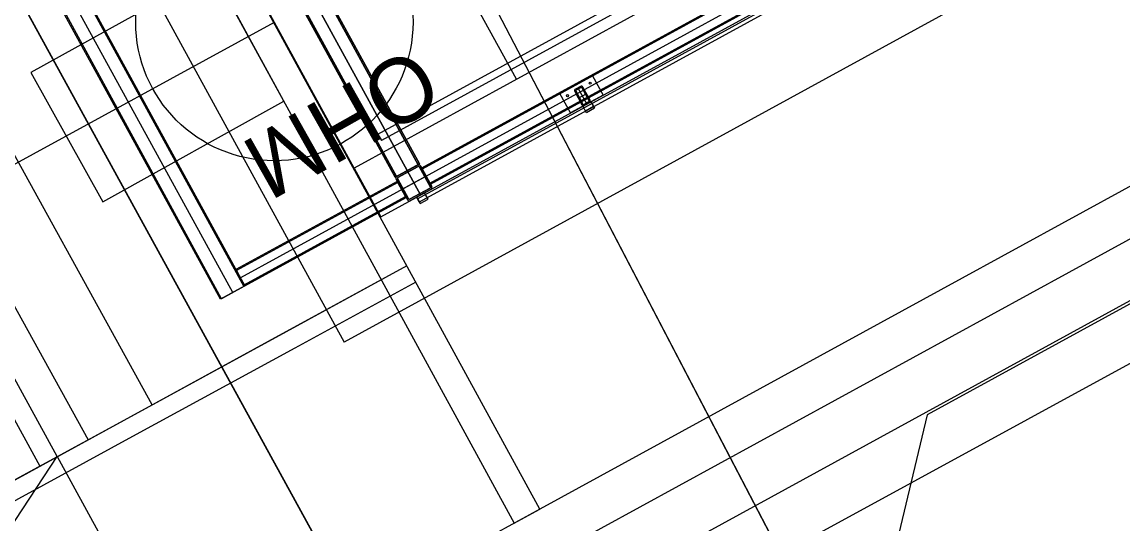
# Model space of a CAD drawing. Extents: x -783978 to -783565, y -1064821 to -1064596.
# Drawn here: x -783787.58 to -783781.62, y -1064696.42 to -1064693.71 of the extents above; entities that cross this region are included whole.
import ezdxf

# ---------------------------------------------------------------- set-up
doc = ezdxf.new("R2010")
doc.units = 0
for name, color, linetype in [('PS 01_01_10', 7, 'Continuous'), ('PS 01_02_501', 7, 'Continuous'), ('PS 01_02_502', 7, 'Continuous'), ('SO 01_20_01', 7, 'Continuous'), ('SO 01_50_01', 7, 'Continuous'), ('SO 01_74_01', 7, 'Continuous'), ('SO 01_79_02', 7, 'Continuous'), ('SO 01_86_02', 7, 'Continuous'), ('SO 01_86_03', 7, 'Continuous'), ('SO 01_86_04', 7, 'Continuous')]:
    doc.layers.add(name, color=color, linetype=linetype)

msp = doc.modelspace()

# ---------------------------------------------------------------- linework, layer by layer
at = {"layer": 'PS 01_01_10'}
msp.add_lwpolyline([(-783718.9415, -1064658.9356), (-783725.9639, -1064662.6889), (-783732.3538, -1064665.9121), (-783735.2095, -1064660.6967), (-783789.362, -1064690.3481), (-783783.8255, -1064700.4409), (-783871.4362, -1064748.4249), (-783875.857, -1064749.8347)], dxfattribs=at)
at = {"layer": 'PS 01_02_501'}
msp.add_lwpolyline([(-783952.3105, -1064789.972), (-783925.027, -1064771.233), (-783922.857, -1064767.935), (-783921.1315, -1064767.225), (-783922.344, -1064769.056), (-783920.816, -1064771.043), (-783917.67, -1064770.417), (-783911.05, -1064766.471), (-783887.429, -1064753.525), (-783871.4362, -1064748.4249), (-783783.8277, -1064700.4386), (-783789.362, -1064690.3481), (-783735.2263, -1064660.7067), (-783727.1901, -1064659.072), (-783724.297, -1064658.4835), (-783715.521, -1064653.988), (-783697.391, -1064644.148), (-783676.268, -1064633.506), (-783655.138, -1064621.894)], dxfattribs=at)
at = {"layer": 'PS 01_02_502'}
msp.add_lwpolyline([(-783952.3105, -1064789.972), (-783925.027, -1064771.233), (-783922.857, -1064767.935), (-783921.1315, -1064767.225), (-783922.344, -1064769.056), (-783920.816, -1064771.043), (-783917.67, -1064770.417), (-783911.05, -1064766.471), (-783887.429, -1064753.525), (-783871.4362, -1064748.4249), (-783783.8277, -1064700.4386), (-783789.362, -1064690.3481), (-783735.2263, -1064660.7067), (-783727.1901, -1064659.072), (-783724.297, -1064658.4835), (-783715.521, -1064653.988), (-783697.391, -1064644.148), (-783676.268, -1064633.506), (-783655.138, -1064621.894)], dxfattribs=at)
at = {"layer": 'SO 01_20_01'}
for p, q in [((-783785.6531, -1064694.3127), (-783737.23, -1064667.82)), ((-783737.0912, -1064667.858), (-783785.7805, -1064694.4964)), ((-783737.2108, -1064667.855), (-783785.6339, -1064694.3478)), ((-783785.6366, -1064694.7596), (-783736.9472, -1064668.1212)), ((-783746.2961, -1064673.8055), (-783785.8354, -1064695.4379)), ((-783787.4671, -1064692.4555), (-783785.8354, -1064695.4379)), ((-783784.9033, -1064694.0165), (-783785.7672, -1064692.4374)), ((-783785.7805, -1064694.4964), (-783786.6445, -1064692.9173)), ((-783785.6531, -1064694.3127), (-783785.6339, -1064694.3478)), ((-783785.6531, -1064694.3127), (-783785.6339, -1064694.3478)), ((-783785.7805, -1064694.4964), (-783785.6366, -1064694.7596))]:
    msp.add_line(p, q, dxfattribs=at)
at = {"layer": 'SO 01_50_01'}
for p, q in [((-783867.1634, -1064737.9103), (-783786.2125, -1064693.7069)), ((-783786.1479, -1064695.3806), (-783785.494, -1064695.0236)), ((-783786.1474, -1064695.3815), (-783785.4935, -1064695.0245)), ((-783786.1, -1064695.4684), (-783785.4461, -1064695.1114)), ((-783787.0256, -1064695.8599), (-783786.1479, -1064695.3806)), ((-783787.0251, -1064695.8608), (-783786.1474, -1064695.3815)), ((-783786.9776, -1064695.9477), (-783786.1, -1064695.4684)), ((-783787.9032, -1064696.3392), (-783787.0256, -1064695.8599)), ((-783787.9028, -1064696.34), (-783787.0251, -1064695.8608)), ((-783787.8553, -1064696.4269), (-783786.9776, -1064695.9477)), ((-783785.429, -1064696.6972), (-783784.7751, -1064696.3401))]:
    msp.add_line(p, q, dxfattribs=at)
for points in [[(-783784.7751, -1064696.3401), (-783745.2333, -1064674.7064)], [(-783784.6553, -1064696.5595), (-783745.1133, -1064674.9257)], [(-783787.3874, -1064696.0575), (-783791.2303, -1064689.0335)], [(-783791.318, -1064689.0815), (-783787.4804, -1064696.1094)], [(-783788.7043, -1064696.7753), (-783787.9847, -1064698.0929), (-783786.6685, -1064697.374), (-783788.3209, -1064697.4774), (-783787.3874, -1064696.0575), (-783786.6685, -1064697.374)]]:
    msp.add_lwpolyline(points, dxfattribs=at)
for points in [[(-783789.5438, -1064687.9418), (-783784.9159, -1064696.417), (-783784.7774, -1064696.3413), (-783789.41, -1064687.8687)], [(-783787.2188, -1064695.9666), (-783786.8738, -1064695.777), (-783790.6896, -1064688.851), (-783791.0399, -1064689.044)], [(-783786.5452, -1064693.4332), (-783787.5293, -1064693.9803), (-783787.1406, -1064694.6795), (-783786.1618, -1064694.1353)]]:
    msp.add_lwpolyline(points, close=True, dxfattribs=at)
msp.add_circle((-783786.2125, -1064693.7069), 0.75, dxfattribs=at)
at = {"layer": 'SO 01_74_01'}
for p, q in [((-783785.4388, -1064694.6628), (-783745.8293, -1064672.9921)), ((-783745.8197, -1064673.0096), (-783785.4292, -1064694.6803)), ((-783786.4428, -1064692.636), (-783785.4348, -1064694.4783)), ((-783785.4348, -1064694.4783), (-783786.4428, -1064692.636)), ((-783786.4358, -1064692.6321), (-783785.4278, -1064694.4744)), ((-783785.4278, -1064694.4744), (-783786.4358, -1064692.6321)), ((-783785.5594, -1064694.5464), (-783786.5674, -1064692.7041)), ((-783786.5674, -1064692.7041), (-783785.5594, -1064694.5464)), ((-783785.5524, -1064694.5426), (-783786.5603, -1064692.7003)), ((-783786.5603, -1064692.7003), (-783785.5524, -1064694.5426)), ((-783787.5067, -1064693.0734), (-783786.3776, -1064695.1372)), ((-783787.5012, -1064693.0704), (-783786.372, -1064695.1342)), ((-783786.5036, -1064695.2062), (-783787.6328, -1064693.1424)), ((-783786.4981, -1064695.2032), (-783787.6272, -1064693.1393)), ((-783782.8498, -1064693.0925), (-783785.4158, -1064694.4964)), ((-783782.8467, -1064693.098), (-783785.4128, -1064694.5019)), ((-783785.3708, -1064694.5786), (-783782.8048, -1064693.1747)), ((-783785.3678, -1064694.5841), (-783782.8018, -1064693.1802)), ((-783784.5443, -1064694.1621), (-783784.5005, -1064694.1381)), ((-783784.5395, -1064694.1708), (-783784.4957, -1064694.1468)), ((-783784.5005, -1064694.1381), (-783784.4813, -1064694.1731)), ((-783784.4957, -1064694.1468), (-783784.4861, -1064694.1644)), ((-783784.5251, -1064694.1971), (-783784.5443, -1064694.1621)), ((-783784.5299, -1064694.1884), (-783784.5395, -1064694.1708)), ((-783784.4861, -1064694.1644), (-783784.5299, -1064694.1884)), ((-783784.4813, -1064694.1731), (-783784.5251, -1064694.1971)), ((-783785.4278, -1064694.4744), (-783785.5594, -1064694.5464)), ((-783785.5594, -1064694.5464), (-783785.4278, -1064694.4744)), ((-783785.4348, -1064694.4783), (-783785.5524, -1064694.5426)), ((-783785.5524, -1064694.5426), (-783785.4348, -1064694.4783)), ((-783785.4158, -1064694.4964), (-783785.3678, -1064694.5841)), ((-783785.4128, -1064694.5019), (-783785.3708, -1064694.5786)), ((-783785.5474, -1064694.5684), (-783786.4203, -1064695.0459)), ((-783785.4994, -1064694.6561), (-783785.5474, -1064694.5684)), ((-783785.5444, -1064694.5739), (-783786.4173, -1064695.0515)), ((-783785.5024, -1064694.6506), (-783785.5444, -1064694.5739)), ((-783785.3997, -1064694.63), (-783785.4436, -1064694.654)), ((-783785.3997, -1064694.63), (-783785.4436, -1064694.654)), ((-783785.3805, -1064694.6651), (-783785.3997, -1064694.63)), ((-783785.3805, -1064694.6651), (-783785.3997, -1064694.63)), ((-783786.3753, -1064695.1281), (-783785.5024, -1064694.6506)), ((-783786.3723, -1064695.1337), (-783785.4994, -1064694.6561)), ((-783785.4436, -1064694.654), (-783785.4244, -1064694.6891)), ((-783785.4436, -1064694.654), (-783785.4244, -1064694.6891)), ((-783785.4292, -1064694.6803), (-783785.4388, -1064694.6628)), ((-783785.4244, -1064694.6891), (-783785.3805, -1064694.6651)), ((-783785.4244, -1064694.6891), (-783785.3805, -1064694.6651)), ((-783786.4203, -1064695.0459), (-783786.3723, -1064695.1337)), ((-783786.4173, -1064695.0515), (-783786.3753, -1064695.1281)), ((-783786.372, -1064695.1342), (-783786.5036, -1064695.2062)), ((-783786.3776, -1064695.1372), (-783786.4981, -1064695.2032))]:
    msp.add_line(p, q, dxfattribs=at)
for points in [[(-783734.0882, -1064666.4715), (-783786.3963, -1064695.0898)], [(-783785.4216, -1064694.642), (-783786.5736, -1064692.5365)], [(-783786.5736, -1064692.5365), (-783785.4216, -1064694.642)], [(-783786.4378, -1064695.1702), (-783787.567, -1064693.1064)], [(-783784.5878, -1064694.0826), (-783784.5489, -1064694.1538)], [(-783784.5568, -1064694.0549), (-783784.584, -1064694.0698)], [(-783784.5823, -1064694.0796), (-783784.5433, -1064694.1507)], [(-783784.5537, -1064694.0604), (-783784.581, -1064694.0753)], [(-783784.5704, -1064694.0623), (-783784.5224, -1064694.1501)], [(-783784.5245, -1064694.0942), (-783784.5683, -1064694.1182)], [(-783784.5105, -1064694.1328), (-783784.5495, -1064694.0616)], [(-783784.505, -1064694.1298), (-783784.5439, -1064694.0586)], [(-783784.5391, -1064694.152), (-783784.5118, -1064694.1371)], [(-783784.536, -1064694.1575), (-783784.5088, -1064694.1426)], [(-783785.5489, -1064694.5407), (-783785.4383, -1064694.4802)], [(-783785.4383, -1064694.4802), (-783785.5489, -1064694.5407)], [(-783785.545, -1064694.5477), (-783785.4345, -1064694.4872)], [(-783785.4345, -1064694.4872), (-783785.545, -1064694.5477)], [(-783785.4216, -1064694.642), (-783785.4936, -1064694.5104)], [(-783785.4291, -1064694.4888), (-783785.3686, -1064694.5993)], [(-783785.3686, -1064694.5993), (-783785.4291, -1064694.4888)], [(-783785.4221, -1064694.485), (-783785.3616, -1064694.5955)], [(-783785.3616, -1064694.5955), (-783785.4221, -1064694.485)], [(-783785.4932, -1064694.6675), (-783785.5537, -1064694.557)], [(-783785.5537, -1064694.557), (-783785.4932, -1064694.6675)], [(-783785.4862, -1064694.6637), (-783785.5466, -1064694.5531)], [(-783785.5466, -1064694.5531), (-783785.4862, -1064694.6637)], [(-783785.3918, -1064694.5402), (-783785.5234, -1064694.6122)], [(-783785.3702, -1064694.6048), (-783785.4807, -1064694.6652)], [(-783785.4807, -1064694.6652), (-783785.3702, -1064694.6048)], [(-783785.3664, -1064694.6118), (-783785.4769, -1064694.6723)], [(-783785.4769, -1064694.6723), (-783785.3664, -1064694.6118)]]:
    msp.add_lwpolyline(points, dxfattribs=at)
msp.add_lwpolyline([(-783784.4347, -1064694.1021), (-783784.6101, -1064694.1981), (-783784.6677, -1064694.0928), (-783784.4923, -1064693.9968)], close=True, dxfattribs=at)
for centre in [(-783784.5042, -1064694.0375), (-783784.627, -1064694.1047)]:
    msp.add_circle(centre, 0.006, dxfattribs=at)
for centre, radius, start, end in [((-783784.5795, -1064694.0781), 0.00945, 118.68349, 208.68349), ((-783784.5795, -1064694.0781), 0.00315, 118.68349, 208.68349), ((-783784.5522, -1064694.0632), 0.00945, 28.68349, 118.68349), ((-783784.5522, -1064694.0632), 0.00315, 28.68349, 118.68349), ((-783784.5406, -1064694.1492), 0.00945, 208.68349, 298.68349), ((-783784.5406, -1064694.1492), 0.00315, 208.68349, 298.68349), ((-783784.5133, -1064694.1343), 0.00315, 298.68349, 28.68349), ((-783784.5133, -1064694.1343), 0.00945, 298.68349, 28.68349), ((-783785.4326, -1064694.4907), 0.012, 28.68349, 118.68349), ((-783785.4326, -1064694.4907), 0.012, 28.68349, 118.68349), ((-783785.4326, -1064694.4907), 0.004, 28.68349, 118.68349), ((-783785.4326, -1064694.4907), 0.004, 28.68349, 118.68349), ((-783785.5431, -1064694.5512), 0.012, 118.68349, 208.68349), ((-783785.5431, -1064694.5512), 0.012, 118.68349, 208.68349), ((-783785.5431, -1064694.5512), 0.004, 118.68349, 208.68349), ((-783785.5431, -1064694.5512), 0.004, 118.68349, 208.68349), ((-783785.3721, -1064694.6013), 0.004, 298.68349, 28.68349), ((-783785.3721, -1064694.6013), 0.004, 298.68349, 28.68349), ((-783785.3721, -1064694.6013), 0.012, 298.68349, 28.68349), ((-783785.3721, -1064694.6013), 0.012, 298.68349, 28.68349), ((-783785.4827, -1064694.6617), 0.012, 208.68349, 298.68349), ((-783785.4827, -1064694.6617), 0.012, 208.68349, 298.68349), ((-783785.4827, -1064694.6617), 0.004, 208.68349, 298.68349), ((-783785.4827, -1064694.6617), 0.004, 208.68349, 298.68349)]:
    msp.add_arc(centre, radius, start, end, dxfattribs=at)
at = {"layer": 'SO 01_79_02'}
msp.add_lwpolyline([(-783745.0819, -1064674.9774), (-783746.507, -1064675.7571), (-783748.1468, -1064676.6636), (-783749.6912, -1064678.1356), (-783784.2571, -1064697.0125), (-783798.19, -1064704.62), (-783800.06, -1064705.37), (-783802.52, -1064706.72), (-783803.71, -1064707.63), (-783853.11, -1064734.61), (-783855.1, -1064735.3), (-783857.05, -1064736.37), (-783858.65, -1064737.64), (-783871.68, -1064744.75), (-783877.0563, -1064744.607), (-783887.4289, -1064744.0617), (-783898.0887, -1064743.4896), (-783899.4205, -1064743.4179)], dxfattribs=at)
at = {"layer": 'SO 01_86_02'}
msp.add_lwpolyline([(-783878.1861, -1064744.2753), (-783875.1286, -1064744.3451), (-783874.6948, -1064744.3279), (-783873.2511, -1064744.1567), (-783872.3143, -1064743.9824), (-783871.2185, -1064743.7022), (-783870.5149, -1064743.4863), (-783869.7975, -1064743.2125), (-783869.1775, -1064742.9745), (-783868.7111, -1064742.7654), (-783868.3945, -1064742.6073), (-783868.078, -1064742.4492), (-783860.9748, -1064738.5687), (-783850.6715, -1064732.6113), (-783846.2461, -1064730.1894), (-783839.9469, -1064727.0857), (-783822.4265, -1064717.4271), (-783813.3562, -1064712.518), (-783804.2851, -1064707.6104), (-783794.4737, -1064702.2521), (-783784.6611, -1064696.8962), (-783775.7336, -1064692.0133), (-783766.8056, -1064687.1312), (-783750.6261, -1064678.2817)], dxfattribs=at)
at = {"layer": 'SO 01_86_03'}
msp.add_line((-783783.3595, -1064696.8031), (-783786.8168, -1064690.1799), dxfattribs=at)
for points in [[(-783722.5212, -1064661.7932), (-783724.8208, -1064663.0486), (-783735.2095, -1064660.6967), (-783787.333, -1064689.2371), (-783786.8168, -1064690.1799), (-783783.3595, -1064696.8031), (-783781.9388, -1064699.4088), (-783783.8277, -1064700.4386), (-783871.4362, -1064748.4249), (-783875.857, -1064749.8347), (-783877.5381, -1064747.3925), (-783875.857, -1064749.8347), (-783887.429, -1064753.525), (-783911.05, -1064766.471), (-783917.67, -1064770.417), (-783920.816, -1064771.043), (-783922.344, -1064769.056), (-783922.498, -1064767.051)], [(-783747.0305, -1064676.621), (-783747.6236, -1064677.108), (-783750.7299, -1064678.7824), (-783751.6662, -1064678.8522), (-783782.6812, -1064695.8307), (-783782.8877, -1064696.6917), (-783783.0615, -1064696.8198), (-783783.3595, -1064696.8031), (-783786.8168, -1064690.1799), (-783787.333, -1064689.2371), (-783735.2095, -1064660.6967), (-783724.8208, -1064663.0486), (-783722.5212, -1064661.7932)]]:
    msp.add_lwpolyline(points, dxfattribs=at)
at = {"layer": 'SO 01_86_04'}
msp.add_lwpolyline([(-783747.063, -1064670.9765), (-783746.9575, -1064671.1681), (-783786.6893, -1064692.8619), (-783786.185, -1064693.7636)], dxfattribs=at)

# ---------------------------------------------------------------- texts
msp.add_text('OHM', height=0.351, rotation=209.46001, dxfattribs=at).set_placement((-783785.455, -1064693.8331))

doc.saveas('drawing.dxf')
